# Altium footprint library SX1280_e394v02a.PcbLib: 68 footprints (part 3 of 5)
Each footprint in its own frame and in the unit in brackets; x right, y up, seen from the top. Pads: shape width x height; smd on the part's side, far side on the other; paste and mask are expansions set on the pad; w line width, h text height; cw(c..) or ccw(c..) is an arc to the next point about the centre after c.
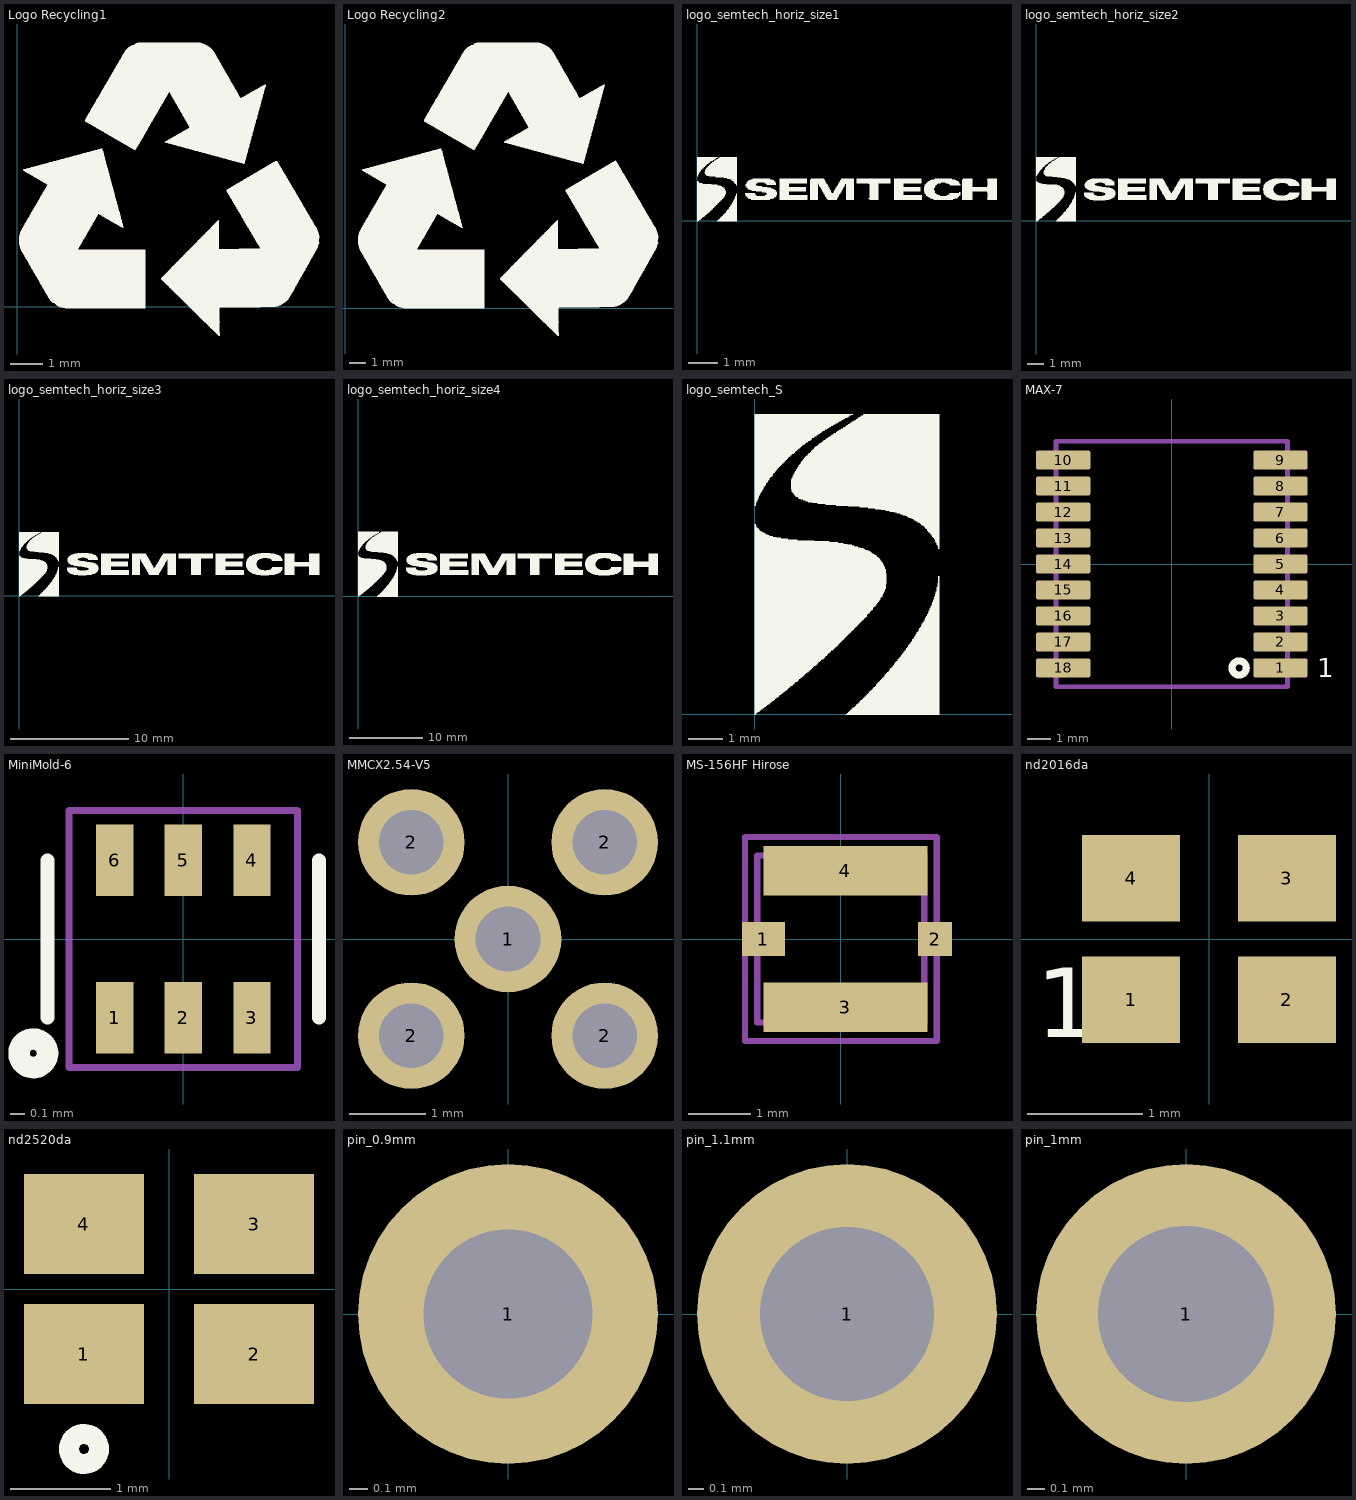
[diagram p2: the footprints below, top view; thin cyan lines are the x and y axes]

## Logo Recycling1 [mm] "Logo Recycling1"
height 0.1
Top Overlay:
  drawing of 3302 lines, arcs and shapes, not listed

## Logo Recycling2 [mm] "Logo Recycling2"
height 0.1
Top Overlay:
  drawing of 3309 lines, arcs and shapes, not listed

## logo_semtech_horiz_size1 [mm] "Logo semtech horizontal - size1 - S"
Top Overlay:
  drawing of 453 lines, arcs and shapes, not listed

## logo_semtech_horiz_size2 [mm] "Logo semtech horizontal - size2 - M"
Top Overlay:
  drawing of 790 lines, arcs and shapes, not listed

## logo_semtech_horiz_size3 [mm] "Logo semtech horizontal - size3 - L"
Top Overlay:
  drawing of 1137 lines, arcs and shapes, not listed

## logo_semtech_horiz_size4 [mm] "Logo semtech horizontal - size4 - XL"
Top Overlay:
  drawing of 1852 lines, arcs and shapes, not listed

## logo_semtech_S [mm] "Logo semtech S size4 - XL"
Top Overlay:
  drawing of 642 lines, arcs and shapes, not listed

## MAX-7 [mm] "MAX-7; GPS U-Blox footprint"
height 4
pads (18):
  rrect20% 2.3x0.8 smd mask+0.05: 1(4.6,-4.4) 2(4.6,-3.3) 3(4.6,-2.2) 4(4.6,-1.1) 5(4.6,0) 6(4.6,1.1) 7(4.6,2.2) 8(4.6,3.3) 9(4.6,4.4) 10(-4.6,4.4) 11(-4.6,3.3) 12(-4.6,2.2) 13(-4.6,1.1) 14(-4.6,0) 15(-4.6,-1.1) 16(-4.6,-2.2) 17(-4.6,-3.3) 18(-4.6,-4.4)
Top Overlay:
  circle w0.3: c2.85,-4.4 r0.3
  text "1" at 6.15,-4.8 h0.8
Mechanical 15:
  lines w0.2: -4.9,-5.2 -4.9,5.2 4.9,5.2 4.9,-5.2 -4.9,-5.2
3D body: height 2.95, standoff 0, extent -4.9,-5.2 4.9,5.2

## MiniMold-6 [mm] "MiniMold-6 Package 1.5x1.1mm"
height 0.55
pads (6):
  rect 0.26x0.5 smd mask+0.05: 1(-0.48,-0.55) 2(0,-0.55) 3(0.48,-0.55) 4(0.48,0.55) 5(0,0.55) 6(-0.48,0.55)
Top Overlay:
  circle w0.15: c-1.05,-0.8 r0.1
  lines w0.1: -0.95,-0.55 -0.95,0.55 ; 0.95,-0.55 0.95,0.55
Mechanical 15:
  lines w0.05: -0.8,-0.9 0.8,-0.9 0.8,0.9 -0.8,0.9 -0.8,-0.9
3D body: height 1, standoff 0, extent -0.75,-0.55 0.75,0.55

## MMCX2.54-V5 [mm] "Connector; RF Coaxial, MMCX, Thru-Hole; 5 Position; Vertical"
height 4.45
pads (5):
  round 1.4 hole 0.85: 1(0,0) 2(-1.27,-1.27) 2(-1.27,1.27) 2(1.27,-1.27) 2(1.27,1.27)

## MS-156HF Hirose [mm] "Hirose MS-156HF receptacle - MS-156HF"
height 1.6
pads (4):
  rect 0.7x0.55 smd mask+0.05: 1(-1.25,0)
  rect 0.55x0.55 smd mask+0.05: 2(1.525,0)
  rect 2.65x0.8 smd mask+0.05: 3(0.075,-1.1) 4(0.075,1.1)
Mechanical 13:
  lines w0.1: -1.55,-1.65 -1.55,1.65 1.55,1.65 1.55,-1.65 -1.55,-1.65
Mechanical 15:
  lines w0.1: -1.35,-1.35 -1.35,1.35 1.35,1.35 1.35,-1.35 -1.35,-1.35
3D body: height 16, standoff 1.3, extent -1.35,-1.35 1.35,1.35

## nd2016da [mm] "Crystal SMD 2.0x1.6mm"
height 0.55
pads (4):
  rect 0.85x0.75 smd mask+0.05: 1(-0.675,-0.525) 2(0.675,-0.525) 3(0.675,0.525) 4(-0.675,0.525)
Top Overlay:
  text "1" at -1.5,-0.85 h0.6
3D body: height 1, standoff 0, extent -1,-0.8 1,0.8

## nd2520da [mm] "Crystal SMD 2.5x2.0mm"
height 0.7
pads (4):
  rect 1.2x1 smd mask+0.05: 1(-0.85,-0.65) 2(0.85,-0.65) 3(0.85,0.65) 4(-0.85,0.65)
Top Overlay:
  circle w0.2: c-0.85,-1.6 r0.15
3D body: height 1, standoff 0, extent -1.25,-1 1.25,1

## pin_0.9mm [mm] "Generic Pin 0.9mm; 1 Lead"
height 1
pads (1):
  round 1.6 hole 0.9 mask+0.05: 1(0,0)

## pin_1.1mm [mm] "Generic Pin 1.1mm; 1 Lead"
height 1
pads (1):
  round 1.9 hole 1.1 mask+0.05: 1(0,0)

## pin_1mm [mm] "Generic Pin 1.1mm; 1 Lead"
height 1
pads (1):
  round 1.7 hole 1 paste+0 mask+0.05: 1(0,0)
